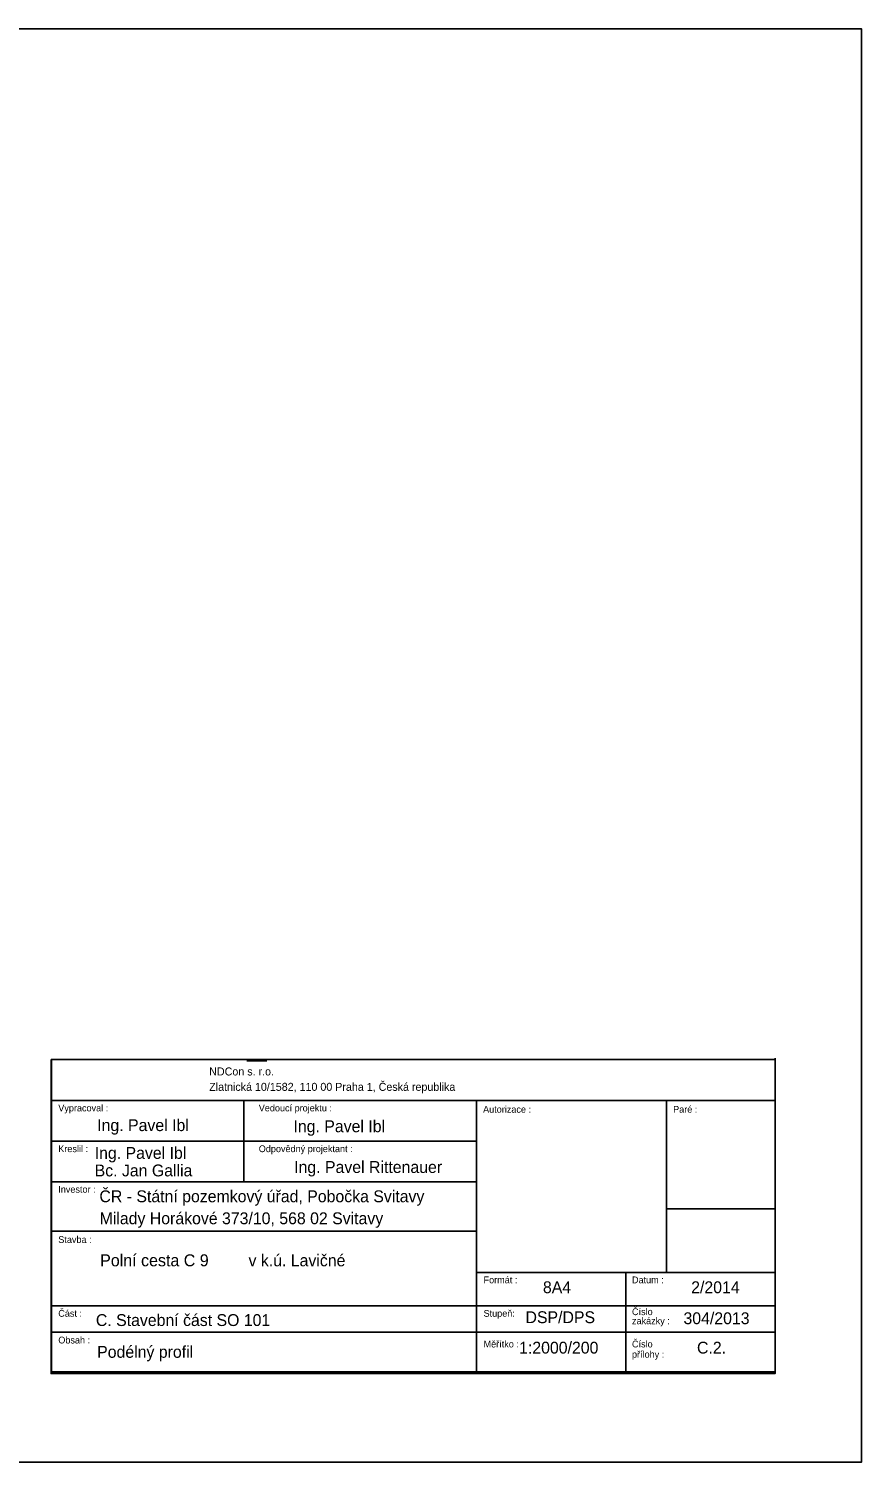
# Model space of a CAD drawing. Extents: x -603528 to -602138, y -1111983 to -1111218.
# Drawn here: x -602556 to -602138, y -1111983 to -1111263 of the extents above; entities that cross this region are included whole.
import ezdxf

# ---------------------------------------------------------------- set-up
doc = ezdxf.new("R2010")
doc.units = 0
for name, color, linetype in [('_netisk', 7, 'Continuous'), ('Default', 7, 'Continuous'), ('rozpiska', 7, 'Continuous')]:
    doc.layers.add(name, color=color, linetype=linetype)

msp = doc.modelspace()

# ---------------------------------------------------------------- linework, layer by layer
at = {"layer": '_netisk'}
msp.add_lwpolyline([(-603527.56, -1111262.74), (-602137.56, -1111262.74), (-602137.56, -1111982.74), (-603527.56, -1111982.74)], close=True, dxfattribs=at)
at = {"layer": 'Default'}
msp.add_line((-602446.3, -1111781.03), (-602436.22, -1111781.03), dxfattribs=at)
msp.add_lwpolyline([(-602544.67, -1111780.49), (-602180.92, -1111780.49), (-602180.92, -1111938.15), (-602544.67, -1111938.15)], close=True, dxfattribs=at)
at = {"layer": 'rozpiska'}
for p, q in [((-602180.92, -1111780.49), (-602544.67, -1111780.49)), ((-602180.92, -1111779.69), (-602180.92, -1111938.15)), ((-602180.92, -1111800.95), (-602544.67, -1111800.95)), ((-602447.78, -1111800.95), (-602447.78, -1111841.87)), ((-602330.97, -1111800.95), (-602330.97, -1111937.36)), ((-602235.49, -1111800.95), (-602235.49, -1111887.34)), ((-602330.97, -1111821.41), (-602544.67, -1111821.41)), ((-602330.97, -1111841.87), (-602544.67, -1111841.87)), ((-602180.92, -1111855.51), (-602235.49, -1111855.51)), ((-602331.07, -1111866.58), (-602544.77, -1111866.58)), ((-602180.92, -1111887.34), (-602330.97, -1111887.34)), ((-602255.95, -1111887.34), (-602255.95, -1111937.36)), ((-602544.67, -1111904.07), (-602180.92, -1111904.07)), ((-602544.67, -1111917.31), (-602180.92, -1111917.31)), ((-602180.92, -1111937.36), (-602544.67, -1111937.36))]:
    msp.add_line(p, q, dxfattribs=at)
msp.add_lwpolyline([(-602544.57, -1111780.49), (-602544.57, -1111937.5)], dxfattribs=at)

# ---------------------------------------------------------------- texts
for s, height, p in [('NDCon s. r.o.', 4.0187, (-602465.25, -1111788.45)), ('Zlatnická 10/1582, 110 00 Praha 1, Česká republika', 4.0187, (-602465.25, -1111796.17)), ('Vypracoval :', 3.4101, (-602541.08, -1111806.5)), ('Vedoucí projektu :', 3.4101, (-602440.34, -1111806.5)), ('Autorizace :', 3.4101, (-602327.62, -1111807.17)), ('Paré :', 3.41, (-602232.14, -1111807.17)), ('Ing. Pavel Ibl', 5.9536, (-602521.52, -1111816.39)), ('Ing. Pavel Ibl', 5.9536, (-602422.9, -1111816.94)), ('Kreslil :', 3.41, (-602541.08, -1111826.96)), ('Odpovědný projektant :', 3.4101, (-602440.34, -1111826.96)), ('Ing. Pavel Ibl', 5.9536, (-602522.78, -1111830.33)), ('Ing. Pavel Rittenauer', 5.9536, (-602422.57, -1111837.41)), ('Bc. Jan Gallia', 5.9536, (-602522.81, -1111839.13)), ('Investor :', 3.41, (-602541.08, -1111847.35)), ('ČR - Státní pozemkový úřad, Pobočka Svitavy', 5.9536, (-602520.41, -1111852.11)), ('Milady Horákové 373/10, 568 02 Svitavy', 5.9536, (-602520.31, -1111863.16)), ('Stavba :', 3.41, (-602541.08, -1111872.56)), ('Polní cesta C 9 ', 6.0137, (-602520.05, -1111884.29)), ('v\xa0k.ú. Lavičné', 5.9536, (-602445.48, -1111884.29)), ('Formát :', 3.41, (-602327.38, -1111892.82)), (' 8A4', 5.954, (-602299.76, -1111897.79)), ('Datum :', 3.41, (-602252.81, -1111892.82)), ('2/2014', 5.954, (-602223.06, -1111897.79)), ('Část :', 3.41, (-602541.08, -1111909.64)), ('C. Stavební část SO 101', 5.9536, (-602522.19, -1111914.28)), ('Stupeň:', 3.41, (-602327.38, -1111909.64)), ('DSP/DPS', 5.954, (-602306.31, -1111912.84)), ('zakázky :', 3.41, (-602252.81, -1111913.38)), ('Číslo', 3.41, (-602252.81, -1111908.81)), ('304/2013', 5.954, (-602226.93, -1111913.36)), ('Obsah :', 3.41, (-602541.08, -1111923.05)), ('Podélný profil', 5.9536, (-602521.55, -1111930.24)), ('Měřítko :', 3.41, (-602327.38, -1111925.04)), ('1:2000/200', 5.954, (-602309.53, -1111928.13)), ('Číslo', 3.41, (-602252.81, -1111925.03)), ('C.2.', 5.954, (-602220.14, -1111928.13)), ('přílohy :', 3.41, (-602252.81, -1111930.21))]:
    msp.add_text(s, height=height, dxfattribs=at).set_placement(p)

doc.saveas('drawing.dxf')
